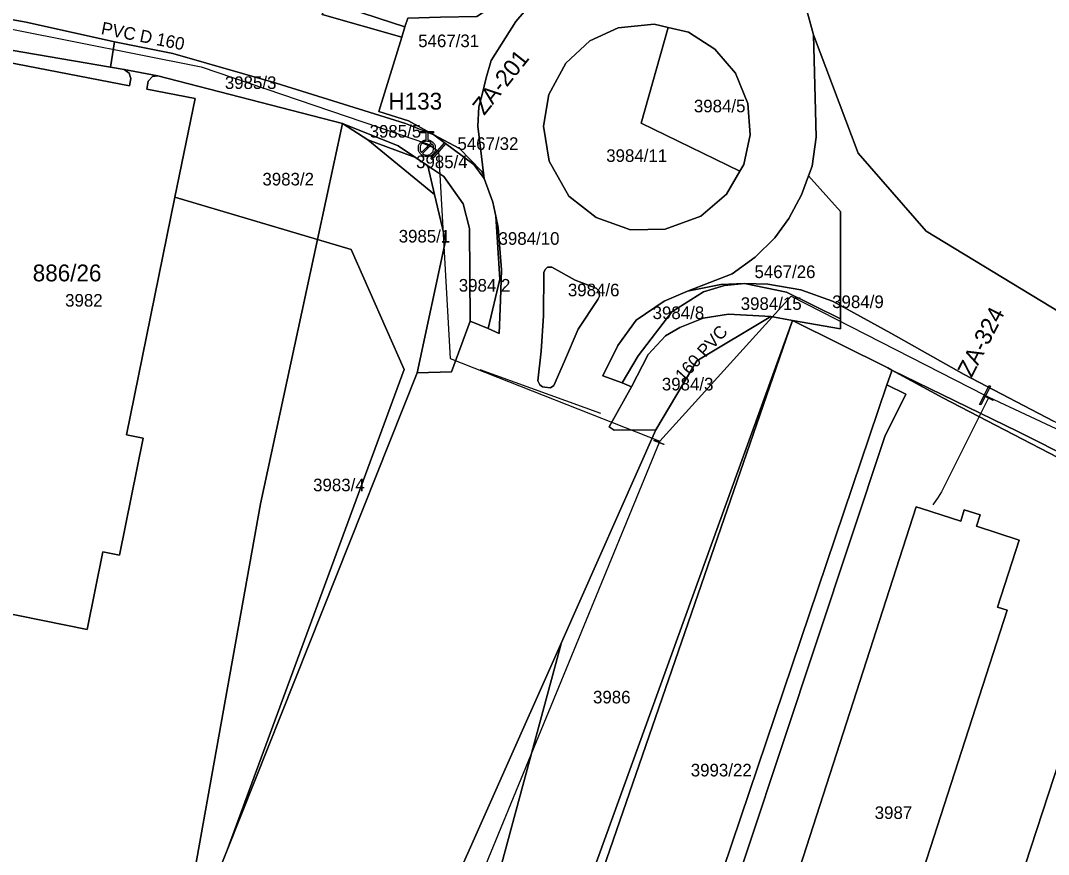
# Model space of a CAD drawing. Extents: x -570104 to -569328, y -1087857 to -1087418.
# Drawn here: x -569780.6 to -569658.3, y -1087670.5 to -1087571.3 of the extents above; entities that cross this region are included whole.
import ezdxf

# ---------------------------------------------------------------- set-up
doc = ezdxf.new("R2010")
doc.units = 0
for name, color, linetype in [('Adresní místo-text', 7, 'Continuous'), ('Armatura - popis', 7, 'Continuous'), ('Armatura vodovodní', 7, 'Continuous'), ('Chránička - vodovod', 7, 'Continuous'), ('Default', 7, 'Continuous'), ('Hydrant', 7, 'Continuous'), ('Označení hydrantu', 7, 'Continuous'), ('Parcela-polygon', 7, 'Continuous'), ('Parcela-text', 7, 'Continuous'), ('Vodovodní přípojka', 7, 'Continuous'), ('Vodovodní řad', 7, 'Continuous'), ('Řad vodovodní popis', 7, 'Continuous')]:
    doc.layers.add(name, color=color, linetype=linetype)

msp = doc.modelspace()

# ---------------------------------------------------------------- linework, layer by layer
at = {"layer": 'Armatura vodovodní'}
for points in [[(-569732.65, -1087585.87), (-569731.5, -1087586.34), (-569731.53, -1087586.42), (-569732.68, -1087585.94), (-569732.65, -1087585.87)], [(-569729.99, -1087585.93), (-569731.62, -1087587.83), (-569731.74, -1087587.72), (-569730.11, -1087585.83), (-569729.99, -1087585.93)], [(-569665.19, -1087614.82), (-569666.33, -1087617.04), (-569666.47, -1087616.97), (-569665.33, -1087614.74), (-569665.19, -1087614.82)], [(-569664.86, -1087616.5), (-569665.98, -1087615.94), (-569665.94, -1087615.87), (-569664.82, -1087616.43), (-569664.86, -1087616.5)], [(-569705.18, -1087621.22), (-569704.02, -1087621.69), (-569704.05, -1087621.76), (-569705.2, -1087621.29), (-569705.18, -1087621.22)]]:
    msp.add_lwpolyline(points, dxfattribs=at)
at = {"layer": 'Chránička - vodovod'}
msp.add_lwpolyline([(-569725.94, -1087612.82), (-569711.59, -1087618.02)], dxfattribs=at)
at = {"layer": 'Default'}
for points in [[(-569732.13, -1087585.49), (-569731.78, -1087585.52), (-569731.52, -1087585.78), (-569731.23, -1087586.08), (-569731.23, -1087586.49), (-569731.23, -1087586.91), (-569731.52, -1087587.2), (-569731.82, -1087587.49), (-569732.23, -1087587.49), (-569732.64, -1087587.49), (-569732.94, -1087587.2), (-569733.23, -1087586.9), (-569733.23, -1087586.49), (-569733.23, -1087586.07), (-569732.94, -1087585.78), (-569732.68, -1087585.52), (-569732.32, -1087585.49)], [(-569731.72, -1087585.85), (-569731.94, -1087585.67), (-569732.23, -1087585.67), (-569732.57, -1087585.67), (-569732.8, -1087585.91), (-569733.04, -1087586.15), (-569733.04, -1087586.48), (-569733.04, -1087586.78), (-569732.87, -1087586.99)], [(-569732.73, -1087587.13), (-569732.52, -1087587.3), (-569732.23, -1087587.3), (-569731.9, -1087587.3), (-569731.66, -1087587.06), (-569731.42, -1087586.83), (-569731.42, -1087586.49), (-569731.42, -1087586.2), (-569731.59, -1087585.98)]]:
    msp.add_open_spline(points, degree=3, dxfattribs=at)
at = {"layer": 'Hydrant'}
for points in [[(-569732.32, -1087585.49), (-569732.32, -1087584.68), (-569733.01, -1087584.67), (-569733.01, -1087584.49), (-569731.44, -1087584.49), (-569731.44, -1087584.68), (-569732.13, -1087584.68), (-569732.13, -1087585.49)], [(-569732.87, -1087586.99), (-569731.72, -1087585.85)], [(-569731.59, -1087585.98), (-569732.73, -1087587.13)]]:
    msp.add_lwpolyline(points, dxfattribs=at)
at = {"layer": 'Parcela-polygon'}
for points in [[(-569657.69, -1087488.2), (-569659, -1087493.2), (-569684.16, -1087553.44), (-569688.63, -1087564.12), (-569686.23, -1087572.99), (-569680.91, -1087587.07), (-569672.82, -1087596.37), (-569655.79, -1087606.73), (-569655.45, -1087604.65), (-569653.75, -1087605.49), (-569636.87, -1087498.32), (-569636.55, -1087495.89)], [(-569791.66, -1087569.4), (-569779.9, -1087571.5), (-569769.4, -1087573.82), (-569762.46, -1087575.23), (-569750.15, -1087578.73), (-569734.75, -1087583.54), (-569731.39, -1087584.88), (-569734.42, -1087583.23), (-569737.96, -1087582.13), (-569735.2, -1087573.26), (-569744.7, -1087570.56), (-569744.5, -1087570.07), (-569744.09, -1087569.05), (-569756.08, -1087566.28), (-569769.73, -1087563.25), (-569786.28, -1087559.57)], [(-569731.2, -1087679), (-569716.23, -1087645.29), (-569705, -1087620), (-569709.95, -1087620.04), (-569710.55, -1087619.64), (-569707.87, -1087614.88), (-569708.99, -1087614.41), (-569711.28, -1087613.57), (-569709.5, -1087609.97), (-569707.32, -1087606.96), (-569703.98, -1087604.67), (-569701.21, -1087603.5), (-569695.92, -1087601.43), (-569693.16, -1087599.47), (-569690.83, -1087597.16), (-569689.18, -1087594.85), (-569687.67, -1087592.04), (-569686.83, -1087589.79), (-569686.4, -1087588.62), (-569685.9, -1087585.16), (-569686.01, -1087582.06), (-569686.08, -1087578.99), (-569686.23, -1087572.99), (-569688.63, -1087564.12)], [(-569787.51, -1087573.83), (-569769.86, -1087576.85), (-569769.4, -1087573.82), (-569779.9, -1087571.5), (-569791.66, -1087569.4)], [(-569719.66, -1087569.11), (-569721.65, -1087571.42), (-569724.57, -1087576.07), (-569725.19, -1087578.13), (-569725.64, -1087580.08), (-569726.04, -1087581.55), (-569726.18, -1087583.85), (-569725.45, -1087589.78), (-569725.41, -1087590.09), (-569724.36, -1087592.89), (-569724.02, -1087594.58), (-569723.75, -1087595.92), (-569723.36, -1087600.95), (-569723.47, -1087604.58), (-569723.61, -1087608.53), (-569724.94, -1087607.96), (-569727.06, -1087607.05), (-569729.31, -1087613.09), (-569733.4, -1087613.2), (-569756, -1087670), (-569762.21, -1087685.64)], [(-569705.19, -1087571.71), (-569703.52, -1087572.12), (-569701.12, -1087572.7), (-569697.96, -1087574.69), (-569695.52, -1087577.55), (-569694.03, -1087581.16), (-569693.77, -1087584.89), (-569694.53, -1087588.43), (-569694.99, -1087589.22), (-569696.58, -1087591.95), (-569699.65, -1087594.57), (-569703.88, -1087596.11), (-569708.01, -1087596.2), (-569712.1, -1087594.72), (-569715.32, -1087592.19), (-569717.67, -1087588.03), (-569718.37, -1087583.87), (-569717.72, -1087580.08), (-569715.68, -1087576.35), (-569712.84, -1087573.71), (-569709.47, -1087572.16), (-569705.19, -1087571.71)], [(-569655.79, -1087606.73), (-569672.82, -1087596.37), (-569680.91, -1087587.07), (-569686.23, -1087572.99), (-569686.08, -1087578.99), (-569686.01, -1087582.06), (-569685.9, -1087585.16), (-569686.4, -1087588.62), (-569686.83, -1087589.79), (-569683, -1087594), (-569683, -1087596.64), (-569683, -1087600.23), (-569683, -1087605.22), (-569677.05, -1087608.51), (-569668.31, -1087613.41), (-569657.69, -1087618.95)], [(-569782.15, -1087576.25), (-569767.59, -1087579.07), (-569767.45, -1087578.18), (-569767.64, -1087577.55), (-569768.23, -1087577.13), (-569769.86, -1087576.85), (-569787.51, -1087573.83)], [(-569793.31, -1087679.13), (-569773.93, -1087685.9), (-569763.73, -1087689.47), (-569763.01, -1087689.72), (-569762.21, -1087685.64), (-569752, -1087628.8), (-569745.23, -1087597.37), (-569762.2, -1087592.33), (-569767.95, -1087620.6), (-569765.97, -1087621.01), (-569768.78, -1087634.92), (-569770.77, -1087634.51), (-569772.66, -1087643.77), (-569791.42, -1087639.95)], [(-569718.31, -1087601.29), (-569718.16, -1087600.93), (-569717.87, -1087600.63), (-569717.38, -1087600.63), (-569714.6, -1087602.19), (-569712.1, -1087603.14), (-569711.74, -1087603.49), (-569711.71, -1087603.72), (-569711.69, -1087604.1), (-569711.89, -1087604.51), (-569714.23, -1087608.02), (-569715.87, -1087611.83), (-569717.14, -1087614.71), (-569717.53, -1087615), (-569718.19, -1087614.94), (-569718.46, -1087614.89), (-569718.77, -1087614.63), (-569718.89, -1087614.41), (-569719.01, -1087614.16), (-569718.61, -1087610.63), (-569718.35, -1087606.43), (-569718.31, -1087601.29)], [(-569746.61, -1087802.34), (-569724.3, -1087738.5), (-569720.63, -1087739.3), (-569710.72, -1087711.45), (-569706.1, -1087706.13), (-569677.75, -1087620.8), (-569675.24, -1087615.77), (-569677.5, -1087614.66), (-569709.27, -1087708.71), (-569712.54, -1087708.01), (-569722.07, -1087703.64), (-569688.74, -1087606.97), (-569723.77, -1087703.85), (-569734.36, -1087733.15), (-569741.51, -1087752.92), (-569751.5, -1087780.56), (-569757.72, -1087797.76)], [(-569656.08, -1087623.85), (-569670.86, -1087616.21), (-569676.9, -1087612.89), (-569676.97, -1087613.11), (-569677.5, -1087614.66), (-569675.24, -1087615.77), (-569677.75, -1087620.8), (-569706.1, -1087706.13), (-569710.72, -1087711.45), (-569720.63, -1087739.3), (-569724.3, -1087738.5), (-569746.61, -1087802.34)], [(-569673.39, -1087629.36), (-569668.72, -1087630.86), (-569668.3, -1087629.52), (-569666.4, -1087630.12), (-569666.82, -1087631.48), (-569661.77, -1087633.12), (-569664.35, -1087641.09), (-569663.2, -1087641.46), (-569677.76, -1087686.51), (-569678.9, -1087686.15), (-569681.99, -1087695.71), (-569684.42, -1087694.89), (-569687.94, -1087706.45), (-569695.48, -1087703.96), (-569691.97, -1087692.47), (-569694.18, -1087691.63), (-569674, -1087629.15), (-569673.39, -1087629.36)], [(-569674.15, -1087711.83), (-569651.41, -1087642.32), (-569633.25, -1087648.27), (-569643.94, -1087679.59), (-569636.12, -1087682.33), (-569634.05, -1087683.06), (-569635, -1087686.54), (-569636.91, -1087686.03), (-569640.33, -1087695.74), (-569648.38, -1087693.02), (-569656.5, -1087717.61), (-569674.15, -1087711.83)]]:
    msp.add_lwpolyline(points, dxfattribs=at)
for points in [[(-569726.3, -1087570.8), (-569717.5, -1087565.1), (-569716.64, -1087563.44), (-569728.64, -1087569.65), (-569744.09, -1087569.05), (-569738.01, -1087571.03), (-569734.83, -1087572.06), (-569734.5, -1087571), (-569730.61, -1087570.91)], [(-569717.5, -1087565.1), (-569726.3, -1087570.8), (-569730.61, -1087570.91), (-569734.5, -1087571), (-569734.83, -1087572.06), (-569735.2, -1087573.26), (-569737.96, -1087582.13), (-569734.42, -1087583.23), (-569731.39, -1087584.88), (-569728.33, -1087586.54), (-569725.74, -1087589.24), (-569725.45, -1087589.78), (-569726.18, -1087583.85), (-569726.04, -1087581.55), (-569725.64, -1087580.08), (-569725.19, -1087578.13), (-569724.57, -1087576.07), (-569721.65, -1087571.42), (-569719.66, -1087569.11)], [(-569744.09, -1087569.05), (-569744.5, -1087570.07), (-569744.7, -1087570.56), (-569735.2, -1087573.26), (-569734.83, -1087572.06), (-569738.01, -1087571.03)], [(-569718.37, -1087583.87), (-569717.67, -1087588.03), (-569715.32, -1087592.19), (-569712.1, -1087594.72), (-569708.01, -1087596.2), (-569703.88, -1087596.11), (-569699.65, -1087594.57), (-569696.58, -1087591.95), (-569694.99, -1087589.22), (-569706.72, -1087583.5), (-569703.52, -1087572.12), (-569705.19, -1087571.71), (-569709.47, -1087572.16), (-569712.84, -1087573.71), (-569715.68, -1087576.35), (-569717.72, -1087580.08)], [(-569701.12, -1087572.7), (-569703.52, -1087572.12), (-569706.72, -1087583.5), (-569694.99, -1087589.22), (-569694.53, -1087588.43), (-569693.77, -1087584.89), (-569694.03, -1087581.16), (-569695.52, -1087577.55), (-569697.96, -1087574.69)], [(-569750.15, -1087578.73), (-569762.46, -1087575.23), (-569769.4, -1087573.82), (-569769.86, -1087576.85), (-569768.23, -1087577.13), (-569764.22, -1087577.88), (-569742.25, -1087583.56), (-569735.66, -1087586.19), (-569733.57, -1087587.61), (-569732.1, -1087588.6), (-569730.21, -1087589.84), (-569727.91, -1087593.12), (-569727.14, -1087596.06), (-569727.06, -1087607.05), (-569724.94, -1087607.96), (-569723.56, -1087602.09), (-569724.02, -1087594.58), (-569724.36, -1087592.89), (-569725.41, -1087590.09), (-569726.63, -1087588.41), (-569731.39, -1087584.88), (-569734.75, -1087583.54)], [(-569767.59, -1087579.07), (-569782.15, -1087576.25), (-569785.01, -1087591.12), (-569788.09, -1087590.53), (-569790, -1087599.4), (-569785.39, -1087600.37), (-569789.36, -1087619.26), (-569787.26, -1087619.8), (-569791.42, -1087639.95), (-569772.66, -1087643.77), (-569770.77, -1087634.51), (-569768.78, -1087634.92), (-569765.97, -1087621.01), (-569767.95, -1087620.6), (-569762.2, -1087592.33), (-569759.81, -1087580.58), (-569765.56, -1087579.46), (-569765.38, -1087578.52), (-569764.88, -1087577.96), (-569764.22, -1087577.88), (-569768.23, -1087577.13), (-569767.64, -1087577.55), (-569767.45, -1087578.18)], [(-569762.2, -1087592.33), (-569745.23, -1087597.37), (-569742.25, -1087583.56), (-569764.22, -1087577.88), (-569764.88, -1087577.96), (-569765.38, -1087578.52), (-569765.56, -1087579.46), (-569759.81, -1087580.58)], [(-569756, -1087670), (-569733.4, -1087613.2), (-569730, -1087597.5), (-569731.3, -1087591.98), (-569739.27, -1087585.51), (-569742.25, -1087583.56), (-569745.23, -1087597.37), (-569741.25, -1087598.55), (-569734.91, -1087612.82)], [(-569733.57, -1087587.61), (-569735.66, -1087586.19), (-569742.25, -1087583.56), (-569739.27, -1087585.51)], [(-569725.45, -1087589.78), (-569725.74, -1087589.24), (-569728.33, -1087586.54), (-569731.39, -1087584.88), (-569726.63, -1087588.41), (-569725.41, -1087590.09)], [(-569733.57, -1087587.61), (-569739.27, -1087585.51), (-569731.3, -1087591.98), (-569732.1, -1087588.6)], [(-569727.91, -1087593.12), (-569730.21, -1087589.84), (-569732.1, -1087588.6), (-569731.3, -1087591.98), (-569730, -1087597.5), (-569733.4, -1087613.2), (-569729.31, -1087613.09), (-569727.06, -1087607.05), (-569727.14, -1087596.06)], [(-569683, -1087596.64), (-569683, -1087594), (-569686.83, -1087589.79), (-569687.67, -1087592.04), (-569689.18, -1087594.85), (-569690.83, -1087597.16), (-569693.16, -1087599.47), (-569695.92, -1087601.43), (-569701.21, -1087603.5), (-569697.26, -1087602.71), (-569694.45, -1087602.58), (-569691.65, -1087602.68), (-569687.72, -1087603.33), (-569683.99, -1087604.67), (-569683, -1087605.22), (-569683, -1087600.23)], [(-569724.94, -1087607.96), (-569723.61, -1087608.53), (-569723.47, -1087604.58), (-569723.36, -1087600.95), (-569723.75, -1087595.92), (-569724.02, -1087594.58), (-569723.56, -1087602.09)], [(-569734.91, -1087612.82), (-569741.25, -1087598.55), (-569745.23, -1087597.37), (-569752, -1087628.8), (-569762.21, -1087685.64), (-569756, -1087670)], [(-569711.69, -1087604.1), (-569711.71, -1087603.72), (-569711.74, -1087603.49), (-569712.1, -1087603.14), (-569714.6, -1087602.19), (-569717.38, -1087600.63), (-569717.87, -1087600.63), (-569718.16, -1087600.93), (-569718.31, -1087601.29), (-569718.35, -1087606.43), (-569718.61, -1087610.63), (-569719.01, -1087614.16), (-569718.89, -1087614.41), (-569718.77, -1087614.63), (-569718.46, -1087614.89), (-569718.19, -1087614.94), (-569717.53, -1087615), (-569717.14, -1087614.71), (-569715.87, -1087611.83), (-569714.23, -1087608.02), (-569711.89, -1087604.51)], [(-569701.21, -1087603.5), (-569703.98, -1087604.67), (-569707.32, -1087606.96), (-569709.5, -1087609.97), (-569711.28, -1087613.57), (-569708.99, -1087614.41), (-569707.07, -1087611.2), (-569703.1, -1087605.94), (-569699.3, -1087603.58), (-569696.83, -1087602.81), (-569694.45, -1087602.58), (-569697.26, -1087602.71)], [(-569708.99, -1087614.41), (-569707.87, -1087614.88), (-569705.91, -1087611.02), (-569703.85, -1087608.81), (-569702.13, -1087607.81), (-569699.36, -1087606.72), (-569696.35, -1087606.25), (-569691.3, -1087606.5), (-569688.74, -1087606.97), (-569683, -1087608), (-569683, -1087606.78), (-569689.44, -1087603.63), (-569694.45, -1087602.58), (-569696.83, -1087602.81), (-569699.3, -1087603.58), (-569703.1, -1087605.94), (-569707.07, -1087611.2)], [(-569683, -1087605.22), (-569683.99, -1087604.67), (-569687.72, -1087603.33), (-569691.65, -1087602.68), (-569694.45, -1087602.58), (-569689.44, -1087603.63), (-569683, -1087606.78)], [(-569578.74, -1087662.05), (-569578.63, -1087662.1), (-569578.84, -1087661.42), (-569580.22, -1087659.19), (-569581.88, -1087657.43), (-569583.46, -1087656.2), (-569596.28, -1087649.69), (-569597.52, -1087649.08), (-569610.29, -1087642.72), (-569631.73, -1087631.98), (-569643.42, -1087626.13), (-569657.69, -1087618.95), (-569668.31, -1087613.41), (-569677.05, -1087608.51), (-569683, -1087605.22), (-569683, -1087606.78), (-569683, -1087608), (-569688.74, -1087606.97), (-569677.4, -1087612.64), (-569676.9, -1087612.89), (-569661.94, -1087620.21)], [(-569691.3, -1087606.5), (-569700.1, -1087611.8), (-569705, -1087620), (-569716.23, -1087645.29), (-569731.33, -1087701.17), (-569727.59, -1087702.09), (-569727.74, -1087702.73), (-569723.77, -1087703.85), (-569688.74, -1087606.97)], [(-569688.74, -1087606.97), (-569722.07, -1087703.64), (-569712.54, -1087708.01), (-569709.27, -1087708.71), (-569677.5, -1087614.66), (-569676.97, -1087613.11), (-569676.9, -1087612.89), (-569677.4, -1087612.64)], [(-569707.87, -1087614.88), (-569710.55, -1087619.64), (-569709.95, -1087620.04), (-569705, -1087620), (-569700.1, -1087611.8), (-569691.3, -1087606.5), (-569696.35, -1087606.25), (-569699.36, -1087606.72), (-569702.13, -1087607.81), (-569703.85, -1087608.81), (-569705.91, -1087611.02)], [(-569578.74, -1087662.05), (-569661.94, -1087620.21), (-569676.9, -1087612.89), (-569670.86, -1087616.21), (-569656.08, -1087623.85), (-569649.02, -1087627.48), (-569621.66, -1087641.16), (-569593.51, -1087655.25), (-569578.36, -1087662.97), (-569578.63, -1087662.1)], [(-569673.39, -1087629.36), (-569674, -1087629.15), (-569694.18, -1087691.63), (-569691.97, -1087692.47), (-569695.48, -1087703.96), (-569687.94, -1087706.45), (-569684.42, -1087694.89), (-569681.99, -1087695.71), (-569678.9, -1087686.15), (-569677.76, -1087686.51), (-569663.2, -1087641.46), (-569664.35, -1087641.09), (-569661.77, -1087633.12), (-569666.82, -1087631.48), (-569666.4, -1087630.12), (-569668.3, -1087629.52), (-569668.72, -1087630.86)], [(-569674.15, -1087711.83), (-569656.5, -1087717.61), (-569648.38, -1087693.02), (-569640.33, -1087695.74), (-569636.91, -1087686.03), (-569635, -1087686.54), (-569634.05, -1087683.06), (-569636.12, -1087682.33), (-569643.94, -1087679.59), (-569633.25, -1087648.27), (-569651.41, -1087642.32)], [(-569735.85, -1087690.34), (-569739.39, -1087698.97), (-569737.69, -1087699.63), (-569731.47, -1087701.68), (-569731.33, -1087701.17), (-569716.23, -1087645.29), (-569731.2, -1087679)]]:
    msp.add_lwpolyline(points, close=True, dxfattribs=at)
at = {"layer": 'Vodovodní přípojka'}
for points in [[(-569665.36, -1087616.11), (-569665.4, -1087616.19), (-569671.01, -1087627.39), (-569671.41, -1087628.01), (-569672.02, -1087628.93)], [(-569704.52, -1087621.35), (-569704.61, -1087621.49), (-569737.51, -1087701.64), (-569737.59, -1087701.85), (-569742.47, -1087713.74)]]:
    msp.add_lwpolyline(points, dxfattribs=at)
at = {"layer": 'Vodovodní řad'}
for points in [[(-569872.09, -1087558.64), (-569840.22, -1087563.16), (-569810.81, -1087567.64), (-569790.51, -1087570.61), (-569789.79, -1087570.73), (-569785.78, -1087571.59), (-569781.39, -1087572.37), (-569759.06, -1087576.8), (-569732.15, -1087585.98), (-569732.05, -1087586.05), (-569730.86, -1087586.83)], [(-569732.23, -1087586.49), (-569732.2, -1087586.4), (-569732.09, -1087586.14), (-569732.06, -1087586.08), (-569732.05, -1087586.05)], [(-569730.86, -1087586.83), (-569729.46, -1087611.52), (-569704.52, -1087621.35)], [(-569704.52, -1087621.35), (-569688.87, -1087604.08), (-569665.83, -1087615.89), (-569665.36, -1087616.11), (-569633.42, -1087631.08), (-569632.62, -1087631.48), (-569601.79, -1087646.96), (-569583.18, -1087656.3), (-569555.45, -1087670.22), (-569542.09, -1087676.92), (-569540.21, -1087677.85)]]:
    msp.add_lwpolyline(points, dxfattribs=at)

# ---------------------------------------------------------------- texts
at = {"layer": 'Adresní místo-text'}
msp.add_text('886/26', height=2, dxfattribs=at).set_placement((-569779.12, -1087602.33))
at = {"layer": 'Armatura - popis'}
for s, rotation, p in [('ZA-201', 51.4451, (-569725.41, -1087582.67)), ('ZA-324', 62.8609, (-569667.42, -1087613.87))]:
    msp.add_text(s, height=2, rotation=rotation, dxfattribs=at).set_placement(p)
at = {"layer": 'Označení hydrantu'}
msp.add_text('H133', height=2, rotation=0.0781, dxfattribs=at).set_placement((-569736.8, -1087581.9))
at = {"layer": 'Parcela-text'}
for s, p in [('5467/31', (-569733.26, -1087574.46)), ('3985/3', (-569756.26, -1087579.44)), ('3984/5', (-569700.46, -1087582.22)), ('3985/5', (-569739.04, -1087585.23)), ('5467/32', (-569728.59, -1087586.69)), ('3985/4', (-569733.51, -1087588.86)), ('3984/11', (-569710.89, -1087588.12)), ('3983/2', (-569751.79, -1087590.92)), ('3985/1', (-569735.58, -1087597.71)), ('3984/10', (-569723.7, -1087597.98)), ('5467/26', (-569693.25, -1087601.94)), ('3984/2', (-569728.43, -1087603.55)), ('3984/6', (-569715.45, -1087604.11)), ('3982', (-569775.26, -1087605.34)), ('3984/15', (-569694.89, -1087605.73)), ('3984/9', (-569684.01, -1087605.51)), ('3984/8', (-569705.37, -1087606.82)), ('3984/3', (-569704.27, -1087615.31)), ('3983/4', (-569745.76, -1087627.31)), ('3986', (-569712.46, -1087652.55)), ('3993/22', (-569700.83, -1087661.24)), ('3987', (-569678.95, -1087666.3))]:
    msp.add_text(s, height=1.5, dxfattribs=at).set_placement(p)
at = {"layer": 'Řad vodovodní popis'}
for s, rotation, p in [('PVC D 160', 348.7794, (-569771.07, -1087572.9)), (' 160 PVC', 47.7979, (-569702.1, -1087614.77))]:
    msp.add_text(s, height=1.5, rotation=rotation, dxfattribs=at).set_placement(p)

doc.saveas('drawing.dxf')
